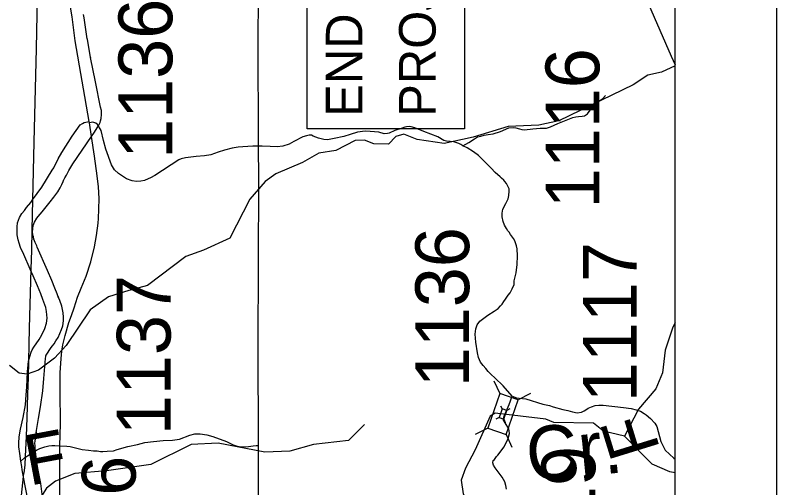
# Model space of a CAD drawing. Extents: x 264770 to 739672, y 157173 to 249791.
# Drawn here: x 727620 to 728336, y 159419 to 159864 of the extents above; entities that cross this region are included whole.
import ezdxf

# ---------------------------------------------------------------- set-up
doc = ezdxf.new("R2010")
doc.units = 0
for name, color, linetype in [('Old_Level_27', 7, 'Continuous'), ('Old_Level_5', 7, 'Continuous'), ('Prop Cable Guiderail Single Face', 7, 'Continuous'), ('Prop Conc 2ft 6in Curb and Gutter', 7, 'Continuous'), ('Prop GRAU 350 Approach CELL', 7, 'Continuous'), ('Prop Guardrail Anchor Unit CELL', 7, 'Continuous'), ('Prop Lane Arrow Right Turn CELL', 7, 'Continuous'), ('Prop Lane Arrow Shared Lt and Thru CELL', 7, 'Continuous'), ('Prop ROW Station Offsets', 7, 'Continuous'), ('Sheet Plot Border Outside CELL', 7, 'Continuous')]:
    doc.layers.add(name, color=color, linetype=linetype)

msp = doc.modelspace()

# ---------------------------------------------------------------- linework, layer by layer
at = {"layer": 'Old_Level_5'}
for points in [[(728240.88, 159816.28), (728228.09, 159810.34), (728215.18, 159807.27), (728201.46, 159798.39), (728131.45, 159764.56), (728112.77, 159760.52), (728084.05, 159759.13), (728051.02, 159749.14), (728023.58, 159743.06), (727998.4, 159746.82), (727985.87, 159751.91), (727978.25, 159749.84), (727971.45, 159742.47), (727957.46, 159742.93), (727948.8, 159746.15), (727940.06, 159745.85), (727921.74, 159736.54), (727905.85, 159734.16), (727890.52, 159725.34), (727865.51, 159714.5), (727855.5, 159707.26), (727840.94, 159690.83), (727822.07, 159654.11), (727797.28, 159642.69), (727780.86, 159636.82), (727744.73, 159609.44), (727727.19, 159604.77), (727708.25, 159598.99), (727691.01, 159586.74), (727668.3, 159553.07), (727657.28, 159541.19), (727642.36, 159530.03), (727631.73, 159526.29), (727624.17, 159527.13), (727615.13, 159534.43)], [(728240.88, 159574.35), (728238.7, 159570.23), (728231.61, 159548.87), (728229.12, 159527.37), (728222.85, 159512.41), (728206.4, 159493.12), (728193.27, 159467.91)], [(728193.27, 159467.91), (728173.62, 159472.65), (728164.12, 159479.96), (728126.72, 159480.62), (728119.2, 159483.78), (728071.56, 159489.46), (728066.92, 159486.7), (728052.97, 159455.09), (728043.68, 159437.89), (728039.77, 159426.35), (728041.58, 159413.46), (728047.77, 159401.58), (728054.96, 159393.65)], [(727948.76, 159478.97), (727933.76, 159463.73), (727900.86, 159460.15), (727878.46, 159453.89), (727855.03, 159452.93), (727811.12, 159461.39), (727785.84, 159459.9), (727748.04, 159441.33), (727706.36, 159435.14), (727676.47, 159432.64), (727658.19, 159425.65), (727649.8, 159418.92), (727642.92, 159407.91)], [(728240.88, 159433.49), (728235.99, 159434.4), (728219.38, 159441.38), (728193.27, 159467.91)]]:
    msp.add_lwpolyline(points, dxfattribs=at)
at = {"layer": 'Prop Conc 2ft 6in Curb and Gutter'}
for p, q in [((728070.46, 159519.87), (728075.93, 159507.88)), ((728104.99, 159507.9), (728093.28, 159501.87)), ((728076.84, 159496.43), (728078.21, 159493.43)), ((728085.47, 159493.44), (728082.54, 159491.93)), ((728075.39, 159485.3), (728072.46, 159483.79)), ((728079.73, 159483.8), (728081.09, 159480.8)), ((728064.66, 159475.36), (728052.94, 159469.33)), ((728082, 159469.35), (728087.48, 159457.37))]:
    msp.add_line(p, q, dxfattribs=at)
msp.add_lwpolyline([(728082, 159469.35), (728093.28, 159501.87), (728075.93, 159507.88), (728064.66, 159475.36)], close=True, dxfattribs=at)
msp.add_lwpolyline([(728079.73, 159483.8), (728082.54, 159491.93), (728078.21, 159493.43), (728075.39, 159485.3), (728079.73, 159483.8)], dxfattribs=at)
at = {"layer": 'Prop GRAU 350 Approach CELL'}
for p, q in [((728240.88, 157172.59), (728240.88, 160226.7)), ((728336.48, 157210.09), (728336.48, 160189.2))]:
    msp.add_line(p, q, dxfattribs=at)
at = {"layer": 'Prop Guardrail Anchor Unit CELL'}
for p, q in [((727849.01, 159983.43), (727848.64, 159840.38)), ((727641.47, 159900.59), (727639.96, 159832.51)), ((727848.64, 159840.38), (727848.93, 159743.2)), ((727848.93, 159743.2), (727849.03, 159707.68)), ((727849.03, 159707.68), (727848.63, 159553.57)), ((727635.56, 159642.69), (727635.09, 159624.95)), ((727848.63, 159553.57), (727848.8, 159459.04)), ((727632.42, 159522.93), (727632.02, 159507.24)), ((727630.62, 159468), (727629.67, 159448.6)), ((727848.8, 159459.04), (727848.9, 159401.21))]:
    msp.add_line(p, q, dxfattribs=at)
for points in [[(728135.49, 160059.15), (728158.93, 160005.68), (728197.74, 159916.13), (728237.26, 159825.28), (728240.88, 159817.21)], [(727639.96, 159832.51), (727638, 159744.52), (727636.73, 159690)], [(727636.73, 159690), (727636.08, 159661.98), (727635.56, 159642.69)], [(727635.09, 159624.95), (727633.6, 159569.44), (727632.42, 159522.93)], [(727632.02, 159507.24), (727631.46, 159485.02), (727630.62, 159468)], [(727629.67, 159448.6), (727629.29, 159440.82), (727628.46, 159432.98)], [(727612.11, 159271.54), (727619.08, 159338.42), (727625.9, 159408.79), (727628.46, 159432.98)]]:
    msp.add_lwpolyline(points, dxfattribs=at)
at = {"layer": 'Prop Lane Arrow Right Turn CELL'}
for points in [[(727676.81, 159839.8), (727673.93, 159862.23), (727670.51, 159882.63), (727664.52, 159923.26)], [(727690.02, 159763.71), (727676.81, 159839.8)], [(727662.49, 159458.75), (727662.84, 159479.43), (727662.69, 159510.23), (727662.53, 159527.33), (727663.48, 159540.95), (727664.11, 159547.76), (727665.22, 159553.61), (727667.44, 159562.64), (727670.77, 159574.91), (727673.3, 159581.48), (727675.84, 159588.61), (727679.01, 159598.59), (727682.33, 159606.98), (727687.25, 159618.46), (727691.52, 159631.76), (727695.01, 159646.01), (727696.91, 159656.62), (727698.34, 159668.34), (727698.81, 159672.61), (727699.13, 159681.32), (727699.29, 159691.3), (727698.65, 159702.23), (727697.39, 159712.76), (727694.93, 159731.32), (727692.14, 159749.72), (727690.18, 159762.64)], [(727690.18, 159762.64), (727690.02, 159763.71)], [(727661.86, 159285.54), (727662.21, 159357.58), (727662.37, 159404.53), (727662.21, 159433.51), (727662.49, 159458.75)]]:
    msp.add_lwpolyline(points, dxfattribs=at)
at = {"layer": 'Prop Lane Arrow Shared Lt and Thru CELL'}
for points in [[(728041.38, 159741.08), (728046.89, 159744.23), (728052.22, 159747.65), (728055.18, 159749.3), (728058.27, 159750.15), (728061.3, 159750.87), (728065.18, 159751.53), (728069.73, 159752.19), (728076.64, 159754.49), (728084.6, 159757.98), (728088.46, 159758.24), (728091.09, 159757.84), (728094.64, 159756.92), (728096.88, 159756.33), (728099.25, 159756), (728107.15, 159756.99), (728113.99, 159757.45), (728120.11, 159757.7), (728123.74, 159758.83), (728130.71, 159761.99), (728144.79, 159767.45), (728147.48, 159768.3), (728150.11, 159768.56), (728153.53, 159768.76), (728155.82, 159769.21), (728158.39, 159771.05), (728161.15, 159774.6), (728163.52, 159778.81), (728166.28, 159781.04), (728169.11, 159783.15), (728170.03, 159783.67), (728172.93, 159785.58), (728175.49, 159788.15)], [(727625.66, 159444.18), (727624.73, 159451.46), (727623.87, 159457.97), (727623.8, 159461.39), (727624.13, 159467.17), (727625.38, 159474.34), (727627.82, 159485.26), (727629.92, 159497.21), (727630.78, 159506.68), (727631.24, 159513.91), (727631.96, 159528.33), (727632.82, 159538.25), (727634.2, 159542.92), (727635.38, 159546.8), (727636.31, 159549.02), (727637.83, 159551.47), (727642.75, 159558.67), (727644.08, 159560.85), (727646.49, 159565.18), (727648.33, 159569.26), (727649.91, 159574.26), (727650.37, 159578.99), (727649.78, 159585.24), (727649.19, 159588.82), (727647.28, 159593.88), (727646.49, 159596.38), (727644.45, 159601.71), (727641.29, 159609.27), (727637.24, 159618.8), (727634.48, 159624.91), (727628.42, 159638.66), (727625.46, 159645.3), (727624.08, 159649.31), (727623.16, 159652.6), (727622.3, 159657.13), (727622.17, 159664.69), (727622.63, 159668.5), (727624.41, 159673.57), (727626.65, 159677.25), (727629.09, 159680.12), (727630.89, 159682.84), (727635.12, 159687.73), (727636.73, 159690), (727645.26, 159701.99), (727655.19, 159718.01), (727656.62, 159720.32), (727660.63, 159728.63), (727664.35, 159734.65), (727673.86, 159750.13), (727681.46, 159760.82), (727683.52, 159762.08), (727685.19, 159762.91), (727690.02, 159763.71)], [(728041.38, 159741.08), (728039.4, 159742.33), (728037.56, 159743.12), (728032.89, 159744.77), (728025.97, 159745.49), (728023.27, 159745.88), (728017.88, 159749.3), (728004.74, 159754.5), (727995.99, 159757.79), (727992.77, 159758.77), (727991.2, 159759.03), (727988.44, 159758.74), (727986.69, 159758.38), (727984.1, 159757.7), (727977.48, 159755.52), (727972.08, 159752.89), (727970.37, 159752.43), (727967.28, 159752.3), (727962.35, 159753.68), (727954.28, 159754.54), (727949.54, 159754.73), (727942.36, 159753.68), (727935.38, 159751.71), (727929.49, 159749.79), (727920.32, 159747.76), (727915.71, 159746.98), (727914.09, 159746.72), (727910.52, 159747), (727905.58, 159748.04), (727903.12, 159749.23), (727900.67, 159750.13), (727899.03, 159750.99), (727896.79, 159751.12), (727894.29, 159750.46), (727890.93, 159749.28), (727882.51, 159744.94), (727878.04, 159742.57), (727871.91, 159740.69), (727866.54, 159740.14), (727860.22, 159740.4), (727852.47, 159740.6), (727843.85, 159740.66), (727834.43, 159740.14), (727829.89, 159739.81), (727824.23, 159738.76), (727817.32, 159736.91), (727811.26, 159734.84), (727804.22, 159732.41), (727798.49, 159731.49), (727790.4, 159731.03), (727780.6, 159729.71), (727776.45, 159728.79), (727774.15, 159727.81), (727751.52, 159712.99), (727747.53, 159710.82), (727745.36, 159709.92), (727741.93, 159708.34), (727738.39, 159707.62), (727734.45, 159707.36), (727730.24, 159708.15), (727725.1, 159709.99), (727717.41, 159714.99), (727713.72, 159718.34), (727710.85, 159723.01), (727705.63, 159737.85), (727703.41, 159745.85), (727701.27, 159755.35), (727697.78, 159760.97), (727696.12, 159762.4), (727693.35, 159763.19), (727690.18, 159762.64)], [(728087.72, 159505.51), (728079.12, 159515.28), (728071.49, 159522.64), (728067.87, 159525.8), (728065.24, 159528.56), (728062.93, 159531.45), (728060.43, 159534.28), (728057.78, 159537.49), (728055.96, 159541.84), (728055.04, 159546.24), (728053.39, 159556.17), (728052.73, 159563.73), (728053.39, 159568.86), (728054.64, 159572.54), (728057.34, 159575.9), (728064.77, 159581.76), (728070.76, 159585.57), (728074.4, 159588.08), (728076.74, 159590.37), (728078.24, 159592.13), (728079.76, 159594.42), (728081.46, 159596.59), (728084.01, 159600.38), (728085.71, 159602.68), (728087.81, 159606.52), (728089.54, 159610.46), (728089.5, 159614.06), (728091.47, 159621.62), (728092.46, 159629.31), (728092.59, 159637.47), (728092.46, 159644.04), (728091.67, 159647), (728090.16, 159651.47), (728088.78, 159653.84), (728086.21, 159657.59), (728084.76, 159659.76), (728083.71, 159661.01), (728082.26, 159663.18), (728080.35, 159666.2), (728079.1, 159669.78), (728078.38, 159674.06), (728078.38, 159677.68), (728078.91, 159681.49), (728081.69, 159686.7), (728083.78, 159690.96), (728084.63, 159694.38), (728084.96, 159698.26), (728084.76, 159700.36), (728083.32, 159703.58), (728082.39, 159705.42), (728080.88, 159707.4), (728079.7, 159708.65), (728077.76, 159710.52), (728076.32, 159711.9), (728071.84, 159715.91), (728067.96, 159719.92), (728064.67, 159723.21), (728060.79, 159727.16), (728056.05, 159731.75), (728051.38, 159735.3), (728045.33, 159738.91), (728041.38, 159741.08)], [(728079.63, 159484.57), (728080.09, 159486.51), (728084.89, 159497.56), (728087.72, 159505.51)], [(728087.72, 159505.51), (728091.73, 159503.91), (728094.18, 159503.51), (728100.5, 159502.86), (728116.63, 159498.06), (728122.69, 159496.54), (728126.17, 159495.43), (728135.45, 159492.8), (728139.99, 159491.88), (728144.43, 159490.63), (728148.7, 159489.84), (728152.78, 159490.56), (728155.41, 159491.68), (728157.08, 159492.58), (728159.13, 159494.05), (728162.19, 159495.56), (728165.87, 159496.74), (728169.16, 159497.14), (728173.23, 159497.07), (728192.31, 159494.77), (728199.63, 159493.78), (728204.3, 159492.66), (728208.44, 159491.22), (728211.8, 159489.25), (728213.64, 159487.93), (728217.85, 159484.45), (728221.8, 159480.05), (728223.71, 159476.9), (728227.52, 159462.96), (728231.51, 159454.58), (728239.6, 159447.15), (728240.88, 159446.25)], [(728082.35, 159417.9), (728081.7, 159421.58), (728080.71, 159424.94), (728078.41, 159429.28), (728071.76, 159437.96), (728070.12, 159440.72), (728069.53, 159442.76), (728069.92, 159444.86), (728070.91, 159445.98), (728071.56, 159446.9), (728073.01, 159448.61), (728074.3, 159450.05), (728080.03, 159457.87), (728083.78, 159465.57), (728085.09, 159470.24), (728084.89, 159472.93), (728084.43, 159474.9), (728081.08, 159480.36), (728079.63, 159482.86), (728079.63, 159484.57)], [(727662.49, 159458.75), (727668.87, 159458.53), (727672.19, 159458.05), (727678.21, 159456.47), (727683.28, 159455.44), (727689.14, 159454.72), (727694.08, 159454.19), (727697.42, 159453.95), (727700.44, 159453.48), (727702.92, 159453.41), (727706.91, 159453.6), (727712.7, 159454.12), (727716.25, 159455.18), (727726.18, 159458), (727735.29, 159460.11), (727742.13, 159461.95), (727750.54, 159462.8), (727759.62, 159463.73), (727768.25, 159463.99), (727774.9, 159465.17), (727784.7, 159468.72), (727789.25, 159469.97), (727794.19, 159470.04), (727800.51, 159469.25), (727806.3, 159467.41), (727819, 159462.71), (727823.54, 159460.53), (727825.27, 159459.63), (727828.28, 159458.65), (727830.94, 159458.23), (727834.97, 159457.8), (727839.75, 159458.17), (727844.17, 159458.65), (727846.93, 159459.13), (727848.8, 159459.04)], [(727625.66, 159444.18), (727629.54, 159447.64), (727633.43, 159450.24), (727637.44, 159452.77), (727640.33, 159454.55), (727643.61, 159456.19), (727648.15, 159457.84), (727652.07, 159458.76), (727654.92, 159459), (727657.77, 159459), (727662.49, 159458.75)], [(727644.01, 159285.38), (727643.63, 159298.19), (727641.61, 159328.12), (727639.87, 159355.36), (727637.37, 159372.77), (727632.33, 159408.62), (727629.87, 159421.03), (727627.63, 159432.6), (727626.98, 159436.16), (727626.45, 159439.31), (727625.66, 159444.18)]]:
    msp.add_lwpolyline(points, dxfattribs=at)
at = {"layer": 'Prop ROW Station Offsets'}
for points in [[(727691.18, 159823.94), (727688.21, 159841.36), (727688.19, 159841.46), (727688.17, 159841.57), (727685.13, 159861.23), (727685.11, 159861.35), (727684.67, 159864.36)], [(727691.18, 159823.94), (727691.14, 159824.13), (727691.21, 159823.74), (727691.18, 159823.94)], [(727698.69, 159759.78), (727699.29, 159760.9), (727700.14, 159762.87), (727700.55, 159764.34), (727701.24, 159766.63), (727701.53, 159770.56), (727701.4, 159774.32), (727700.71, 159777.29), (727695.73, 159801.29), (727691.18, 159823.94)], [(727692.14, 159749.72), (727694.31, 159752.91), (727698.18, 159758.82), (727698.69, 159759.78)], [(727636.74, 159658.09), (727636.76, 159659.46), (727636.79, 159660.73), (727636.81, 159662.06), (727636.97, 159663.57), (727637.19, 159665.31), (727637.41, 159666.24), (727637.54, 159666.67), (727637.92, 159667.56), (727638.61, 159669.13), (727640.78, 159672.83), (727641.89, 159674.5), (727645.68, 159678.88), (727653.2, 159688.12), (727656.84, 159692.7), (727660.39, 159697.62), (727662.54, 159701.4), (727664.08, 159704.66), (727665.39, 159707.38), (727666.12, 159709.35), (727666.26, 159709.63), (727667.03, 159710.96), (727668.48, 159713.32), (727670.94, 159717.67), (727674.56, 159723.9), (727692.14, 159749.72)], [(727636.74, 159658.09), (727636.73, 159658.39), (727636.73, 159657.79), (727636.74, 159658.09)], [(727641.09, 159645.71), (727640.62, 159646.78), (727639.22, 159650.12), (727638, 159653.2), (727637.43, 159655.37), (727636.74, 159657.95), (727636.74, 159658.09)], [(727660.88, 159599), (727659.87, 159601.63), (727657.65, 159606.96), (727654.74, 159614.28), (727650.72, 159623.69), (727650.67, 159623.79), (727641.09, 159645.71)], [(727640.05, 159471.23), (727642.13, 159484.43), (727644.19, 159495.45), (727646.42, 159510.46), (727647.32, 159521.99), (727647.32, 159522.01), (727648.77, 159540.78), (727649.1, 159542.89), (727649.23, 159543.73), (727649.37, 159543.96), (727654.32, 159551.2), (727655.32, 159552.84), (727656.96, 159554.83), (727658.7, 159557.48), (727660.88, 159560.8), (727662.39, 159564.31), (727663.88, 159568.04), (727665.09, 159571.73), (727665.69, 159576.23), (727665.76, 159579.72), (727665.38, 159583.91), (727664.69, 159586.91), (727664.19, 159590.26), (727662.49, 159595.31), (727660.88, 159599)], [(727660.88, 159599), (727660.76, 159599.28), (727660.99, 159598.72), (727660.88, 159599)], [(727640.05, 159471.23), (727640.09, 159471.85), (727639.95, 159470.62), (727640.05, 159471.23)], [(727639.4, 159453.5), (727639.32, 159453.98), (727639.1, 159456.33), (727638.99, 159458.67), (727638.91, 159461.3), (727639.11, 159463.29), (727639.78, 159467.24), (727640.05, 159471.23)], [(727645.94, 159410.69), (727644.34, 159423.19), (727641.96, 159435.73), (727640.65, 159443.21), (727640.11, 159448.4), (727640.1, 159448.5), (727640.08, 159448.61), (727639.9, 159450.65), (727639.4, 159453.5)]]:
    msp.add_lwpolyline(points, dxfattribs=at)
at = {"layer": 'Sheet Plot Border Outside CELL'}
msp.add_lwpolyline([(727895.01, 159757.02), (727895.01, 160011.41), (728042.96, 160011.41), (728042.96, 159757.02)], close=True, dxfattribs=at)

# ---------------------------------------------------------------- texts
at = {"layer": 'Old_Level_27'}
msp.add_text('Cr.', height=50.625, rotation=5.64741, dxfattribs=at).set_placement((728103.31, 159425.04))
at = {"layer": 'Prop Cable Guiderail Single Face'}
for s, p in [('1136', (727768.1, 159728.69)), ('1116', (728169.66, 159682.15)), ('1136', (728047.23, 159513.83)), ('1117', (728204.78, 159499.84)), ('1137', (727766.51, 159468.85)), ('1119', (728165.82, 159307.99)), ('1136', (727733.65, 159298.83))]:
    msp.add_text(s, height=50.625, rotation=90, dxfattribs=at).set_placement(p)
at = {"layer": 'Prop Guardrail Anchor Unit CELL'}
for rotation, p in [(107.15749, (728227.06, 159455.64)), (10.61075, (727633.79, 159421.17))]:
    msp.add_text('F', height=47.33, rotation=rotation, dxfattribs=at).set_placement(p)
at = {"layer": 'Sheet Plot Border Outside CELL'}
for s, p in [('PROJECT', (728015.72, 159768.24)), ('END', (727946.87, 159768.24))]:
    msp.add_text(s, height=34.425, rotation=90, dxfattribs=at).set_placement(p)

doc.saveas('drawing.dxf')
